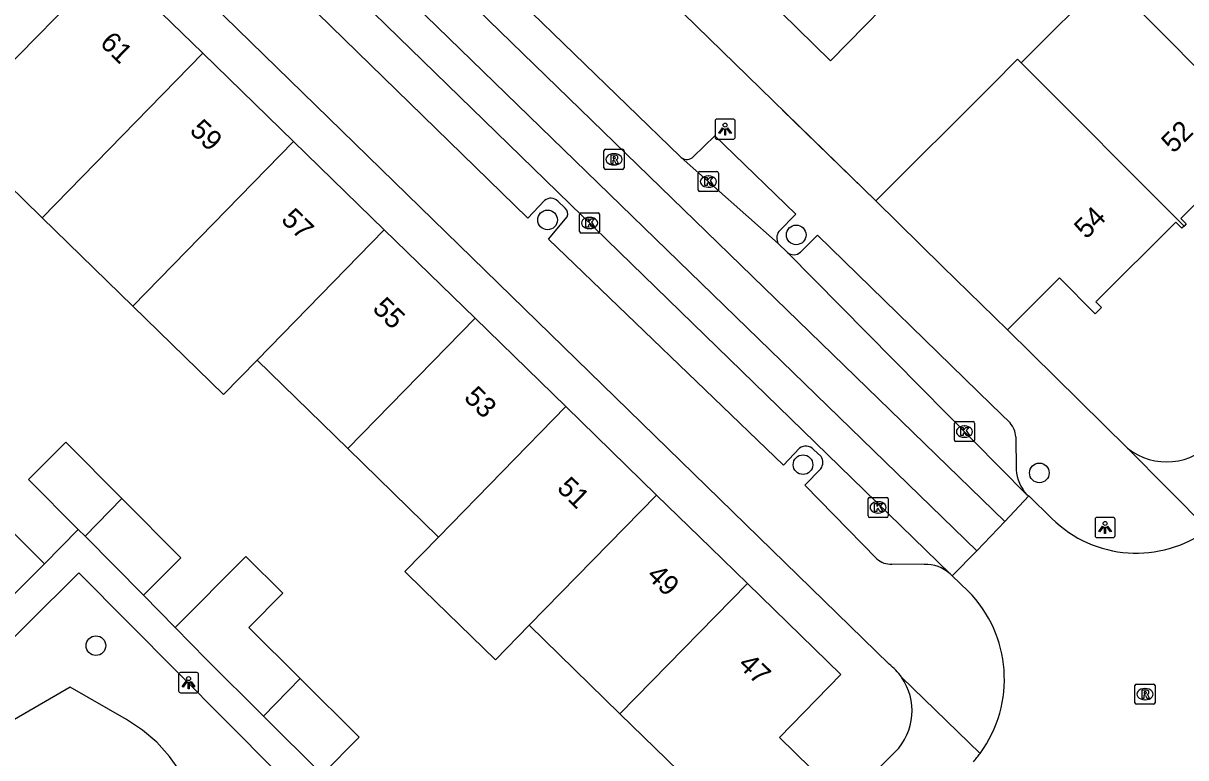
# Model space of a CAD drawing. Extents: x 159222 to 160346, y 381249 to 382166.
# Drawn here: x 159940.8 to 159998.6, y 381771.7 to 381808.2 of the extents above; entities that cross this region are included whole.
import ezdxf

# ---------------------------------------------------------------- set-up
doc = ezdxf.new("R2010")
doc.units = 0
for name, color, linetype in [('IMGEO_Boom', 7, 'Continuous'), ('IMGEO_Groenvoorziening', 7, 'Continuous'), ('IMGEO_Kolk', 7, 'Continuous'), ('IMGEO_Lichtpunt', 7, 'Continuous'), ('IMGEO_Muur', 7, 'Continuous'), ('IMGEO_Pand', 7, 'Continuous'), ('IMGEO_Pand_nummerreeks', 7, 'Continuous'), ('IMGEO_Rijbaan_lokaal_gesloten', 7, 'Continuous'), ('IMGEO_Rijbaan_lokaal_open', 7, 'Continuous'), ('IMGEO_Rioolput', 7, 'Continuous'), ('IMGEO_Voetpad_open', 7, 'Continuous')]:
    doc.layers.add(name, color=color, linetype=linetype)

msp = doc.modelspace()

# ---------------------------------------------------------------- linework, layer by layer
at = {"layer": 'IMGEO_Boom'}
for centre in [(159966.885, 381798.443), (159979.252, 381797.697), (159979.592, 381786.268), (159991.349, 381785.858), (159944.419, 381777.266)]:
    msp.add_circle(centre, 0.489, dxfattribs=at)
at = {"layer": 'IMGEO_Groenvoorziening'}
msp.add_lwpolyline([(159948.619, 381770.988), (159948.081, 381771.76), (159947.45, 381772.458), (159946.735, 381773.069), (159945.948, 381773.585), (159943.144, 381775.2), (159939.851, 381773.288), (159939.093, 381770.568)], dxfattribs=at)
at = {"layer": 'IMGEO_Kolk'}
for p, q in [((159974.384, 381799.925), (159974.384, 381800.777)), ((159974.459, 381800.851), (159975.311, 381800.851)), ((159974.872, 381800.631), (159974.897, 381800.631)), ((159975.385, 381800.777), (159975.385, 381799.925)), ((159974.895, 381800.071), (159974.87, 381800.071)), ((159975.311, 381799.851), (159974.459, 381799.851)), ((159968.551, 381798.791), (159969.403, 381798.791)), ((159968.476, 381797.865), (159968.476, 381798.717)), ((159968.964, 381798.571), (159968.989, 381798.571)), ((159969.477, 381798.717), (159969.477, 381797.865)), ((159969.403, 381797.791), (159968.551, 381797.791)), ((159968.987, 381798.011), (159968.962, 381798.011)), ((159987.122, 381787.488), (159987.122, 381788.34)), ((159987.197, 381788.414), (159988.049, 381788.414)), ((159988.123, 381788.34), (159988.123, 381787.488)), ((159987.61, 381788.194), (159987.635, 381788.194)), ((159988.049, 381787.414), (159987.197, 381787.414)), ((159987.633, 381787.634), (159987.608, 381787.634)), ((159982.827, 381783.717), (159982.827, 381784.569)), ((159982.902, 381784.643), (159983.754, 381784.643)), ((159983.315, 381784.423), (159983.34, 381784.423)), ((159983.828, 381784.569), (159983.828, 381783.717)), ((159983.338, 381783.863), (159983.313, 381783.863)), ((159983.754, 381783.643), (159982.902, 381783.643))]:
    msp.add_line(p, q, dxfattribs=at)
for points in [[(159974.384, 381799.925), (159974.384, 381800.777)], [(159974.459, 381800.851), (159975.311, 381800.851)], [(159974.705, 381800.551), (159974.828, 381800.551), (159974.828, 381800.4), (159974.958, 381800.551), (159975.122, 381800.551), (159974.976, 381800.4), (159975.129, 381800.151), (159974.977, 381800.151), (159974.892, 381800.315), (159974.828, 381800.248), (159974.828, 381800.151), (159974.705, 381800.151), (159974.705, 381800.551)], [(159975.385, 381800.777), (159975.385, 381799.925)], [(159975.311, 381799.851), (159974.459, 381799.851)], [(159968.551, 381798.791), (159969.403, 381798.791)], [(159968.476, 381797.865), (159968.476, 381798.717)], [(159968.797, 381798.491), (159968.92, 381798.491), (159968.92, 381798.34), (159969.05, 381798.491), (159969.214, 381798.491), (159969.068, 381798.34), (159969.221, 381798.091), (159969.069, 381798.091), (159968.984, 381798.255), (159968.92, 381798.188), (159968.92, 381798.091), (159968.797, 381798.091), (159968.797, 381798.491)], [(159969.477, 381798.717), (159969.477, 381797.865)], [(159969.403, 381797.791), (159968.551, 381797.791)], [(159987.122, 381787.488), (159987.122, 381788.34)], [(159987.197, 381788.414), (159988.049, 381788.414)], [(159988.123, 381788.34), (159988.123, 381787.488)], [(159987.443, 381788.114), (159987.566, 381788.114), (159987.566, 381787.963), (159987.696, 381788.114), (159987.86, 381788.114), (159987.714, 381787.963), (159987.867, 381787.714), (159987.715, 381787.714), (159987.63, 381787.878), (159987.566, 381787.811), (159987.566, 381787.714), (159987.443, 381787.714), (159987.443, 381788.114)], [(159988.049, 381787.414), (159987.197, 381787.414)], [(159982.827, 381783.717), (159982.827, 381784.569)], [(159982.902, 381784.643), (159983.754, 381784.643)], [(159983.148, 381784.343), (159983.271, 381784.343), (159983.271, 381784.192), (159983.401, 381784.343), (159983.565, 381784.343), (159983.419, 381784.192), (159983.572, 381783.943), (159983.42, 381783.943), (159983.335, 381784.107), (159983.271, 381784.04), (159983.271, 381783.943), (159983.148, 381783.943), (159983.148, 381784.343)], [(159983.828, 381784.569), (159983.828, 381783.717)], [(159983.754, 381783.643), (159982.902, 381783.643)]]:
    msp.add_lwpolyline(points, dxfattribs=at)
for centre, start, end in [((159974.461, 381800.775), 91.55205, 178.44795), ((159974.461, 381800.775), 91.55205, 178.44795), ((159975.309, 381800.775), 1.55205, 88.44795), ((159975.309, 381800.775), 1.55205, 88.44795), ((159974.461, 381799.927), 181.55205, 268.44795), ((159974.461, 381799.927), 181.55205, 268.44795), ((159975.309, 381799.927), 271.55205, 358.44795), ((159975.309, 381799.927), 271.55205, 358.44795), ((159968.553, 381798.715), 91.55205, 178.44795), ((159968.553, 381798.715), 91.55205, 178.44795), ((159969.401, 381798.715), 1.55205, 88.44795), ((159969.401, 381798.715), 1.55205, 88.44795), ((159968.553, 381797.867), 181.55205, 268.44795), ((159968.553, 381797.867), 181.55205, 268.44795), ((159969.401, 381797.867), 271.55205, 358.44795), ((159969.401, 381797.867), 271.55205, 358.44795), ((159987.199, 381788.338), 91.55205, 178.44795), ((159987.199, 381788.338), 91.55205, 178.44795), ((159988.047, 381788.338), 1.55205, 88.44795), ((159988.047, 381788.338), 1.55205, 88.44795), ((159987.199, 381787.49), 181.55205, 268.44795), ((159987.199, 381787.49), 181.55205, 268.44795), ((159988.047, 381787.49), 271.55205, 358.44795), ((159988.047, 381787.49), 271.55205, 358.44795), ((159982.904, 381784.567), 91.55205, 178.44795), ((159982.904, 381784.567), 91.55205, 178.44795), ((159983.752, 381784.567), 1.55205, 88.44795), ((159983.752, 381784.567), 1.55205, 88.44795), ((159982.904, 381783.719), 181.55205, 268.44795), ((159982.904, 381783.719), 181.55205, 268.44795), ((159983.752, 381783.719), 271.55205, 358.44795), ((159983.752, 381783.719), 271.55205, 358.44795)]:
    msp.add_arc(centre, 0.0765, start, end, dxfattribs=at)
for centre, major_axis, ratio, start_param, end_param in [((159974.871, 381800.351), (-0.387, 0.002), 0.722429, 4.712389, 7.853982), ((159974.896, 381800.351), (-0.39, 0.002), 0.717154, 1.570796, 4.712389), ((159968.963, 381798.291), (-0.387, 0.002), 0.722429, 4.712389, 7.853982), ((159968.988, 381798.291), (-0.39, 0.002), 0.717154, 1.570796, 4.712389), ((159987.609, 381787.914), (-0.387, 0.002), 0.722429, 4.712389, 7.853982), ((159987.634, 381787.914), (-0.39, 0.002), 0.717154, 1.570796, 4.712389), ((159983.314, 381784.143), (-0.387, 0.002), 0.722429, 4.712389, 7.853982), ((159983.339, 381784.143), (-0.39, 0.002), 0.717154, 1.570796, 4.712389)]:
    msp.add_ellipse(centre, major_axis=major_axis, ratio=ratio, start_param=start_param, end_param=end_param, dxfattribs=at)
at = {"layer": 'IMGEO_Lichtpunt'}
for p, q in [((159975.22, 381803.363), (159975.22, 381802.556)), ((159975.22, 381803.363), (159975.22, 381802.556)), ((159976.122, 381803.458), (159975.314, 381803.458)), ((159976.122, 381803.458), (159975.314, 381803.458)), ((159976.216, 381802.556), (159976.216, 381803.363)), ((159976.216, 381802.556), (159976.216, 381803.363)), ((159975.314, 381802.462), (159976.122, 381802.462)), ((159975.314, 381802.462), (159976.122, 381802.462)), ((159994.121, 381783.547), (159994.121, 381782.74)), ((159994.121, 381783.547), (159994.121, 381782.74)), ((159995.023, 381783.642), (159994.215, 381783.642)), ((159995.023, 381783.642), (159994.215, 381783.642)), ((159995.117, 381782.74), (159995.117, 381783.547)), ((159995.117, 381782.74), (159995.117, 381783.547)), ((159994.215, 381782.646), (159995.023, 381782.646)), ((159994.215, 381782.646), (159995.023, 381782.646)), ((159948.529, 381775.828), (159948.529, 381775.021)), ((159948.529, 381775.828), (159948.529, 381775.021)), ((159949.431, 381775.923), (159948.623, 381775.923)), ((159949.431, 381775.923), (159948.623, 381775.923)), ((159949.525, 381775.021), (159949.525, 381775.828)), ((159949.525, 381775.021), (159949.525, 381775.828)), ((159948.623, 381774.927), (159949.431, 381774.927)), ((159948.623, 381774.927), (159949.431, 381774.927))]:
    msp.add_line(p, q, dxfattribs=at)
for points in [[(159975.594, 381803.027), (159975.633, 381802.999), (159975.445, 381802.737), (159975.407, 381802.764), (159975.594, 381803.027)], [(159975.696, 381802.979), (159975.743, 381802.979), (159975.743, 381802.657), (159975.696, 381802.657), (159975.696, 381802.979)], [(159975.806, 381802.999), (159975.844, 381803.026), (159976.031, 381802.764), (159975.992, 381802.736), (159975.806, 381802.999)], [(159994.495, 381783.211), (159994.534, 381783.183), (159994.346, 381782.921), (159994.308, 381782.948), (159994.495, 381783.211)], [(159994.597, 381783.163), (159994.644, 381783.163), (159994.644, 381782.841), (159994.597, 381782.841), (159994.597, 381783.163)], [(159994.707, 381783.183), (159994.745, 381783.21), (159994.932, 381782.948), (159994.893, 381782.92), (159994.707, 381783.183)], [(159948.903, 381775.492), (159948.942, 381775.464), (159948.754, 381775.202), (159948.716, 381775.229), (159948.903, 381775.492)], [(159949.005, 381775.444), (159949.052, 381775.444), (159949.052, 381775.122), (159949.005, 381775.122), (159949.005, 381775.444)], [(159949.115, 381775.464), (159949.153, 381775.491), (159949.34, 381775.229), (159949.301, 381775.201), (159949.115, 381775.464)]]:
    msp.add_lwpolyline(points, dxfattribs=at)
for centre in [(159975.719, 381803.161), (159994.62, 381783.345), (159949.028, 381775.626)]:
    msp.add_circle(centre, 0.0994, dxfattribs=at)
for centre, start, end in [((159975.314, 381803.363), 90, 180), ((159975.314, 381803.363), 90, 180), ((159976.122, 381803.363), 0, 90), ((159976.122, 381803.363), 0, 90), ((159975.314, 381802.556), 180, 270), ((159975.314, 381802.556), 180, 270), ((159976.122, 381802.556), 270, 0), ((159976.122, 381802.556), 270, 360), ((159994.215, 381783.547), 90, 180), ((159994.215, 381783.547), 90, 180), ((159995.023, 381783.547), 0, 90), ((159995.023, 381783.547), 0, 90), ((159994.215, 381782.74), 180, 270), ((159994.215, 381782.74), 180, 270), ((159995.023, 381782.74), 270, 0), ((159995.023, 381782.74), 270, 360), ((159948.623, 381775.828), 90, 180), ((159948.623, 381775.828), 90, 180), ((159949.431, 381775.828), 0, 90), ((159949.431, 381775.828), 0, 90), ((159948.623, 381775.021), 180, 270), ((159948.623, 381775.021), 180, 270), ((159949.431, 381775.021), 270, 0), ((159949.431, 381775.021), 270, 360)]:
    msp.add_arc(centre, 0.0946, start, end, dxfattribs=at)
at = {"layer": 'IMGEO_Muur'}
msp.add_lwpolyline([(159983.209, 381799.393), (159978.568, 381803.9)], dxfattribs=at)
at = {"layer": 'IMGEO_Pand'}
for points in [[(159982.782, 381813.158), (159985.248, 381810.755), (159980.966, 381806.361), (159978.5, 381808.765)], [(159941.743, 381798.547), (159940.812, 381799.455), (159937.231, 381802.944), (159938.899, 381804.656), (159938.756, 381804.796), (159945.095, 381811.253), (159949.735, 381806.735)], [(159994.679, 381810.489), (159990.44, 381806.263)], [(159994.679, 381810.489), (159996.907, 381808.288), (160000, 381805.186), (160002.813, 381802.35)], [(159941.743, 381798.547), (159949.735, 381806.735)], [(159949.735, 381806.735), (159954.249, 381802.34)], [(159990.44, 381806.263), (159990.269, 381806.435), (159988.997, 381805.166), (159983.209, 381799.393)], [(159998.544, 381798.137), (159990.44, 381806.263)], [(159946.254, 381794.149), (159954.249, 381802.34)], [(159954.249, 381802.34), (159958.763, 381797.945)], [(160002.813, 381802.35), (160002.696, 381802.233), (160002.395, 381802.536), (160000, 381800.124), (159998.386, 381798.515), (159998.654, 381798.246), (159998.544, 381798.137)], [(159989.764, 381792.975), (159986.539, 381796.132), (159983.209, 381799.393)], [(159946.254, 381794.149), (159941.743, 381798.547)], [(159998.544, 381798.137), (159998.433, 381798.027), (159998.133, 381798.328), (159994.165, 381794.372), (159994.446, 381794.091), (159994.131, 381793.777), (159992.354, 381795.558), (159989.764, 381792.975)], [(159952.433, 381791.463), (159958.763, 381797.945)], [(159958.763, 381797.945), (159963.276, 381793.55)], [(159952.433, 381791.463), (159950.766, 381789.752), (159946.254, 381794.149)], [(159963.276, 381793.55), (159956.945, 381787.066)], [(159963.276, 381793.55), (159967.79, 381789.155)], [(159956.945, 381787.066), (159952.433, 381791.463)], [(159961.457, 381782.669), (159967.79, 381789.155)], [(159967.79, 381789.155), (159972.303, 381784.76)], [(159943.542, 381783.048), (159941.066, 381785.537), (159941.917, 381786.383), (159942.924, 381787.385), (159945.712, 381784.581)], [(159961.457, 381782.669), (159956.945, 381787.066)], [(159943.882, 381782.706), (159945.712, 381784.581)], [(159945.712, 381784.581), (159948.65, 381781.627), (159946.792, 381779.78)], [(159972.303, 381784.76), (159965.975, 381778.278)], [(159972.303, 381784.76), (159974.984, 381782.15), (159976.824, 381780.357)], [(159937.123, 381780.317), (159940.008, 381783.19), (159941.857, 381781.334)], [(159943.882, 381782.706), (159943.542, 381783.048)], [(159946.792, 381779.78), (159943.882, 381782.706)], [(159965.975, 381778.278), (159964.301, 381776.56), (159960.72, 381780.049), (159959.789, 381780.957), (159961.457, 381782.669)], [(159948.356, 381778.17), (159951.879, 381781.709), (159953.722, 381779.875), (159952.027, 381778.173), (159954.583, 381775.629)], [(159941.857, 381781.334), (159938.971, 381778.46)], [(159976.824, 381780.357), (159981.472, 381775.827), (159978.42, 381772.695), (159981.516, 381769.668), (159978.097, 381766.158), (159977.839, 381766.41), (159978.042, 381766.618), (159975.203, 381769.393), (159975.149, 381769.338), (159970.487, 381773.881)], [(159976.824, 381780.357), (159970.487, 381773.881)], [(159952.753, 381773.755), (159949.916, 381776.578), (159948.356, 381778.17)], [(159970.487, 381773.881), (159965.975, 381778.278)], [(159952.753, 381773.755), (159954.583, 381775.629)], [(159954.583, 381775.629), (159957.521, 381772.706), (159955.673, 381770.849)], [(159955.673, 381770.849), (159952.753, 381773.755)]]:
    msp.add_lwpolyline(points, dxfattribs=at)
at = {"layer": 'IMGEO_Rijbaan_lokaal_gesloten'}
for points in [[(159989.625, 381783.442), (159950.234, 381821.714), (159951.509, 381823.058)], [(159947.654, 381819.044), (159948.826, 381820.271), (159988.232, 381781.989)], [(159947.87, 381818.841), (159986.909, 381780.832)], [(159964.779, 381810.044), (159965.566, 381809.266), (159973.484, 381801.591), (159973.538, 381801.544)], [(159978.362, 381797.273), (159973.538, 381801.544)], [(159978.362, 381797.273), (159978.819, 381796.815)], [(159990.73, 381784.772), (159978.819, 381796.815)], [(159990.828, 381784.721), (159989.625, 381783.442)], [(159990.73, 381784.772), (159990.828, 381784.721)], [(159988.232, 381781.989), (159987.009, 381780.736)], [(159987.009, 381780.736), (159986.909, 381780.832)]]:
    msp.add_lwpolyline(points, dxfattribs=at)
at = {"layer": 'IMGEO_Rijbaan_lokaal_open'}
for points in [[(159990.828, 381784.721), (159991.973, 381783.59)], [(159988.232, 381781.989), (159989.625, 381783.442)], [(159987.807, 381779.983), (159987.009, 381780.736)]]:
    msp.add_lwpolyline(points, dxfattribs=at)
for centre, radius, start, end in [((159996.178, 381787.86), 5.993, 225.43572, 306.5439), ((159983.369, 381775.597), 6.24, 323.76203, 44.66633), ((159983.395, 381775.584), 6.211, 318.80124, 323.71097)]:
    msp.add_arc(centre, radius, start, end, dxfattribs=at)
at = {"layer": 'IMGEO_Rioolput'}
for p, q in [((159969.69, 381801.032), (159969.69, 381801.884)), ((159969.765, 381801.958), (159970.617, 381801.958)), ((159970.178, 381801.738), (159970.203, 381801.738)), ((159970.691, 381801.884), (159970.691, 381801.032)), ((159970.201, 381801.178), (159970.176, 381801.178)), ((159970.617, 381800.958), (159969.765, 381800.958)), ((159996.104, 381774.428), (159996.104, 381775.28)), ((159996.179, 381775.354), (159997.031, 381775.354)), ((159996.592, 381775.134), (159996.617, 381775.134)), ((159997.105, 381775.28), (159997.105, 381774.428)), ((159996.615, 381774.574), (159996.59, 381774.574)), ((159997.031, 381774.354), (159996.179, 381774.354))]:
    msp.add_line(p, q, dxfattribs=at)
for points in [[(159969.69, 381801.032), (159969.69, 381801.884)], [(159969.765, 381801.958), (159970.617, 381801.958)], [(159970.279, 381801.656), (159970.027, 381801.658), (159970.027, 381801.258)], [(159970.691, 381801.884), (159970.691, 381801.032)], [(159970.027, 381801.258), (159970.151, 381801.258), (159970.151, 381801.42), (159970.162, 381801.42)], [(159970.205, 381801.577), (159970.151, 381801.577), (159970.151, 381801.496)], [(159970.151, 381801.496), (159970.203, 381801.496)], [(159970.209, 381801.391), (159970.28, 381801.258), (159970.42, 381801.258), (159970.355, 381801.384)], [(159970.617, 381800.958), (159969.765, 381800.958)], [(159996.104, 381774.428), (159996.104, 381775.28)], [(159996.179, 381775.354), (159997.031, 381775.354)], [(159996.693, 381775.052), (159996.441, 381775.054), (159996.441, 381774.654)], [(159997.105, 381775.28), (159997.105, 381774.428)], [(159996.441, 381774.654), (159996.565, 381774.654), (159996.565, 381774.816), (159996.576, 381774.816)], [(159996.619, 381774.973), (159996.565, 381774.973), (159996.565, 381774.892)], [(159996.565, 381774.892), (159996.617, 381774.892)], [(159996.623, 381774.787), (159996.694, 381774.654), (159996.834, 381774.654), (159996.769, 381774.78)], [(159997.031, 381774.354), (159996.179, 381774.354)]]:
    msp.add_lwpolyline(points, dxfattribs=at)
for centre, radius, start, end in [((159969.767, 381801.882), 0.0765, 91.55205, 178.44795), ((159969.767, 381801.882), 0.0765, 91.55205, 178.44795), ((159970.278, 381801.546), 0.109, 350.36119, 89.41601), ((159970.615, 381801.882), 0.0765, 1.55205, 88.44795), ((159970.615, 381801.882), 0.0765, 1.55205, 88.44795), ((159970.161, 381801.367), 0.0533, 26.02933, 88.69889), ((159970.187, 381801.685), 0.19, 274.7715, 282.96867), ((159970.211, 381801.481), 0.0964, 77.00612, 93.18647), ((159970.225, 381801.538), 0.0378, 276.66336, 79.67722), ((159970.276, 381801.546), 0.112, 277.58423, 350.98172), ((159970.26, 381801.331), 0.108, 29.51342, 73.79051), ((159969.767, 381801.034), 0.0765, 181.55205, 268.44795), ((159969.767, 381801.034), 0.0765, 181.55205, 268.44795), ((159970.615, 381801.034), 0.0765, 271.55205, 358.44795), ((159970.615, 381801.034), 0.0765, 271.55205, 358.44795), ((159996.181, 381775.278), 0.0765, 91.55205, 178.44795), ((159996.181, 381775.278), 0.0765, 91.55205, 178.44795), ((159996.692, 381774.942), 0.109, 350.36119, 89.41601), ((159997.029, 381775.278), 0.0765, 1.55205, 88.44795), ((159997.029, 381775.278), 0.0765, 1.55205, 88.44795), ((159996.575, 381774.763), 0.0533, 26.02933, 88.69889), ((159996.601, 381775.081), 0.19, 274.7715, 282.96867), ((159996.625, 381774.877), 0.0964, 77.00612, 93.18647), ((159996.639, 381774.934), 0.0378, 276.66336, 79.67722), ((159996.69, 381774.942), 0.112, 277.58423, 350.98172), ((159996.674, 381774.727), 0.108, 29.51342, 73.79051), ((159996.181, 381774.43), 0.0765, 181.55205, 268.44795), ((159996.181, 381774.43), 0.0765, 181.55205, 268.44795), ((159997.029, 381774.43), 0.0765, 271.55205, 358.44795), ((159997.029, 381774.43), 0.0765, 271.55205, 358.44795)]:
    msp.add_arc(centre, radius, start, end, dxfattribs=at)
for centre, major_axis, ratio, start_param, end_param in [((159970.177, 381801.458), (-0.387, 0.002), 0.722429, 4.712389, 7.853982), ((159970.202, 381801.458), (-0.39, 0.002), 0.717154, 1.570796, 4.712389), ((159996.591, 381774.854), (-0.387, 0.002), 0.722429, 4.712389, 7.853982), ((159996.616, 381774.854), (-0.39, 0.002), 0.717154, 1.570796, 4.712389)]:
    msp.add_ellipse(centre, major_axis=major_axis, ratio=ratio, start_param=start_param, end_param=end_param, dxfattribs=at)
at = {"layer": 'IMGEO_Voetpad_open'}
for points in [[(159944.981, 381814.27), (159983.879, 381776.342)], [(159966.737, 381799.408), (159965.903, 381798.536), (159954.156, 381810.01), (159954.806, 381810.982)], [(159983.209, 381799.393), (159973.639, 381808.707)], [(159974.151, 381801.597), (159974.655, 381802.096), (159975.2, 381802.635), (159975.663, 381802.187), (159979.23, 381798.735), (159978.389, 381797.866)], [(159967.763, 381799.021), (159967.39, 381799.379)], [(159979.419, 381787.084), (159978.629, 381786.239), (159966.94, 381797.483), (159967.857, 381798.602)], [(159979.462, 381796.841), (159980.196, 381797.567), (159980.308, 381797.678), (159988.948, 381789.265), (159989.894, 381788.343)], [(159989.764, 381792.975), (159995.728, 381787.091)], [(159990.177, 381787.661), (159990.198, 381786.016)], [(159980.488, 381786.674), (159980.12, 381787.025)], [(159995.728, 381787.091), (159999.747, 381783.045)], [(159983.261, 381781.589), (159979.677, 381785.254), (159980.485, 381786.066)], [(159941.857, 381781.334), (159943.542, 381783.048)], [(159968.081, 381756.217), (159943.572, 381780.882), (159925.447, 381762.9)], [(159985.616, 381781.311), (159984.016, 381781.325)], [(159946.792, 381779.78), (159948.356, 381778.17)], [(159984.485, 381775.706), (159988.402, 381771.908)], [(159969.165, 381757.287), (159981.918, 381769.715), (159984.182, 381771.978)]]:
    msp.add_lwpolyline(points, dxfattribs=at)
for centre, radius, start, end in [((159973.815, 381801.908), 0.457, 232.65907, 317.22395), ((159967.048, 381799.043), 0.48, 44.49388, 130.42041), ((159967.526, 381798.748), 0.361, 336.18327, 49.1059), ((159978.828, 381797.549), 0.541, 144.14653, 210.63958), ((159979.125, 381797.216), 0.504, 232.63816, 311.99288), ((159989.015, 381787.579), 1.164, 4.05136, 41.02124), ((159979.735, 381786.645), 0.541, 44.64284, 125.73519), ((159997.673, 381789.523), 3.114, 231.33848, 319.68862), ((159980.015, 381786.372), 0.561, 326.9083, 32.52629), ((159992.238, 381786.153), 2.045, 183.8329, 222.47531), ((159983.935, 381782.306), 0.984, 226.74891, 274.7048), ((159985.675, 381779.486), 1.826, 47.49482, 91.85025), ((159982.093, 381774.034), 2.919, 34.96062, 52.272), ((159982.079, 381774.025), 2.935, 315.76489, 34.9419)]:
    msp.add_arc(centre, radius, start, end, dxfattribs=at)

# ---------------------------------------------------------------- texts
at = {"layer": 'IMGEO_Pand_nummerreeks'}
for s, rotation, p in [('61', 315.75881, (159944.568, 381807.187)), ('59', 315.75881, (159949.034, 381802.837)), ('52', 45.08562, (159998.021, 381801.717)), ('57', 315.75881, (159953.582, 381798.409)), ('54', 44.91399, (159993.682, 381797.45)), ('55', 315.75881, (159958.129, 381793.981)), ('53', 315.75881, (159962.676, 381789.552)), ('51', 315.75881, (159967.304, 381785.046)), ('49', 315.75881, (159971.77, 381780.696)), ('47', 315.75881, (159976.317, 381776.268))]:
    msp.add_text(s, height=1, rotation=rotation, dxfattribs=at).set_placement(p)

doc.saveas('drawing.dxf')
